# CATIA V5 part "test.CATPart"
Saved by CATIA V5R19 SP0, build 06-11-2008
Part number: Part1
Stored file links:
  F:\554\test.CATPart
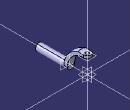
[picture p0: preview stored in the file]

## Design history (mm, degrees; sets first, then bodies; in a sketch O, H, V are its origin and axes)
Body1 (main body)
  Sketch1 on yz-plane, origin (0, 0, 0), H (0, 1, 0), V (0, 0, 1)
    arc A1 centre (0, 0) radius 55 from (0, 55) to (-55, 0) ccw
    point P1 (-55, 0)
    point P2 (0, 55)
    line L1 (0, 55) -> (0, 0)
    line L2 (0, 0) -> (-55, 0)
    radius A1 = 55
    coincidence: P1 H, P2 V
    vertical: L1 V
    horizontal: L2 H
  Shaft1: profile Sketch1, axis Sketch1.H, angle 90, second angle 90
  Sketch2 on yz-plane, origin (0, 0, 0), H (0, 1, 0), V (0, 0, 1)
    point P1 (0, 0)
    line L1 (0, 0) -> (-132.951, 0)
    line L2 (-132.951, 0) -> (-132.951, 10)
    line L3 (-132.951, 10) -> (0, 10)
    line L4 (0, 10) -> (0, 0)
    reference projected line E1 (0, 53.3762) -> (0, 0) from edge [face of Shaft1 from Sketch1.A1 | face of Shaft1 from Sketch1.L1]
    length L2 = 10
    coincidence: P1 H, L4 E1
    horizontal: L1 H, L3 H
    vertical: L2 V, L4 V
  Shaft2: profile Sketch2, axis Sketch2.H, angle 0, second angle 360
  Sketch3 on zx-plane, origin (0, 0, 0), H (-1, 0, 0), V (0, 0, 1)
    line L1 (10, 72.1496) -> (90, 72.1496)
    line L2 (90, 72.1496) -> (90, -19.84)
    line L3 (90, -19.84) -> (10, -19.84)
    line L4 (10, -19.84) -> (10, 72.1496)
    line L5 (-90, 72.1496) -> (-10, 72.1496)
    line L6 (-10, -19.84) -> (-90, -19.84)
    line L7 (-10, 72.1496) -> (-10, -19.84)
    line L8 (-90, -19.84) -> (-90, 72.1496)
    length L1 = 80
    length L5 = 80
    distance L7 L4 = 20
    horizontal: L1 H, L3 H, L5 H, L6 H
    vertical: L2 V, L4 V, L7 V, L8 V
    symmetry: L4 L7 V
    coincidence: L1 L5, L3 L6
    parallelism: L2 L8
  Pocket1: profile Sketch3, direction (0, -1, 0), through (limit type 3)
  Sketch4 on face of Pocket1 from Sketch3.L7, origin (10, 0, 0), H (0, 1, 0), V (0, 0, 1)
    arc A1 centre (0, 0) radius 45 from (0, 45) to (-45, 0) ccw
    point P1 (-45, 0)
    point P2 (0, 45)
    line L1 (0, 45) -> (0, -39.8895)
    line L2 (0, -39.8895) -> (-45, -39.8895)
    line L3 (-45, -39.8895) -> (-45, 0)
    radius A1 = 45
    coincidence: P1 H, P2 V
    vertical: L1 V
    horizontal: L2 H
    tangency: L3 A1
  Pocket2: profile Sketch4, direction (1, 0, 0), through (limit type 3)
  Plane1: type Angle, Angle 90, Direction edge [face of Pocket2 from Sketch4.A1 | face of Shaft2], RefPlane face of Shaft2
  Sketch5 on Plane1, origin (0, 0, 45), H (1, 0, 0), V (0, 1, 0)
    arc A1 centre (0, 0) radius 10 from (10, 0) to (-10, 0) ccw
    point P1 (-10, 0)
    point P2 (10, 0)
    line L1 (10, 0) -> (-10, 0)
    reference projected point E1 (-10, 0) from vertex [face of Shaft2 | face of Pocket2 from Sketch4.A1 | face of Pocket1 from Sketch3.L4]
    coincidence: P1 H, P2 H, P1 E1
    horizontal: L1 H
  Pad1: profile Sketch5, direction (0, 0, 1), length 6.8
  Sketch6 on yz-plane, origin (0, 0, 0), H (0, 1, 0), V (0, 0, 1)
    line L1 (-17.1874, 59.8134) -> (21.7787, 59.8134)
    line L2 (21.7787, 59.8134) -> (21.7787, 51.8)
    line L3 (21.7787, 51.8) -> (-17.1874, 51.8)
    line L4 (-17.1874, 51.8) -> (-17.1874, 59.8134)
    reference projected line E1 (0, 51.8) -> (10, 51.8) from edge [face of Pad1 from Sketch5.A1 | end face of Pad1]
    horizontal: L1 H, L3 H
    vertical: L2 V, L4 V
    coincidence: L3 E1
  Pocket3: profile Sketch6, direction (-1, 0, 0), length 20, mirrored extent
  Sketch7 on face of Pocket3, origin (0, 0, 51.8), H (1, 0, 0), V (0, 1, 0)
    circle A1 centre (0, 0) radius 5
    radius A1 = 5
  Pocket4: profile Sketch7, direction (0, 0, -1), through (limit type 3)
  Point1: type Center, Curve edge [face of Pocket2 from Sketch4.L3 | face of Shaft2 from Sketch2.L3]
  Line1: type Normal, RefSkin face of Pocket2 from Sketch4.L3, Start 0, End 20, RefPoint Point1
  Plane2: type Offset, Offset 60, RefPlane zx-plane, reversed
  Point2: type Center, Curve edge [face of Pocket3 | face of Pocket4 from Sketch7.A1]
  Line2: type Normal, RefSkin face of Pocket3, Start 0, End 20, RefPoint Point2
  Plane3: type 2Lines, Element1 Line1, Element2 Line2
  Point3: type OnPlane, Support Plane3, Direction (0, 1, 0), H 0, V 0
  Line3: type Normal, RefSkin Plane3, Start 0, End 20, RefPoint Point3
